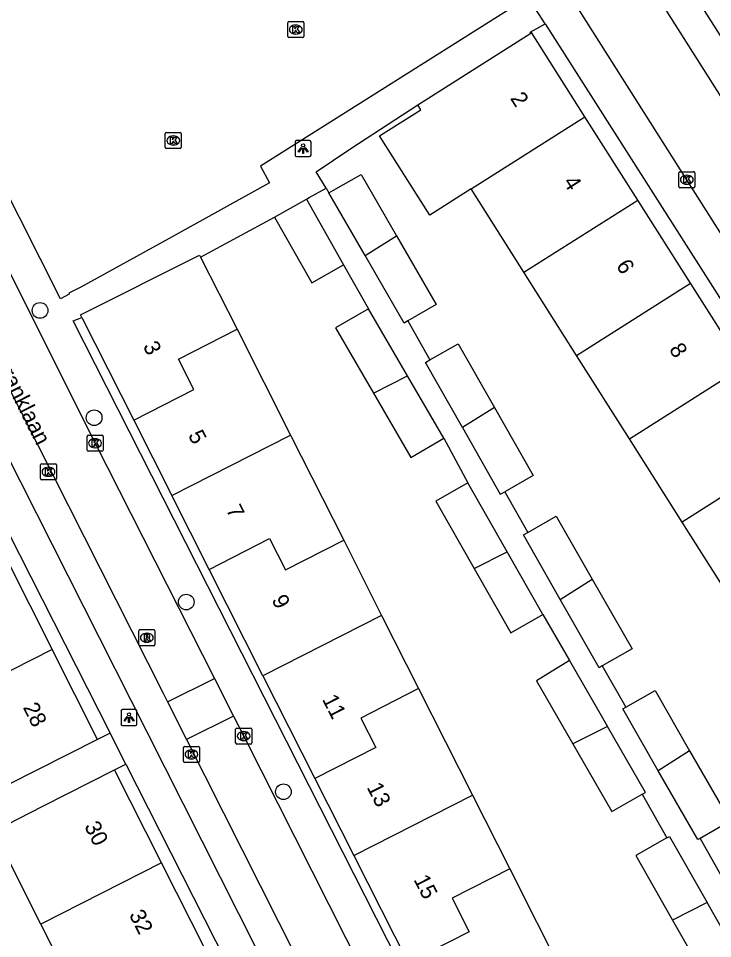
# Model space of a CAD drawing. Extents: x 162347 to 162868, y 381221 to 381813.
# Drawn here: x 162450 to 162493.3, y 381573.3 to 381630.7 of the extents above; entities that cross this region are included whole.
import ezdxf

# ---------------------------------------------------------------- set-up
doc = ezdxf.new("R2010")
doc.units = 0
for name, color, linetype in [('IMGEO_Boom', 7, 'Continuous'), ('IMGEO_Kolk', 7, 'Continuous'), ('IMGEO_Lichtpunt', 7, 'Continuous'), ('IMGEO_Openbare_ruimte_label', 7, 'Continuous'), ('IMGEO_Pand', 7, 'Continuous'), ('IMGEO_Pand_nummerreeks', 7, 'Continuous'), ('IMGEO_Rijbaan_lokaal_open', 7, 'Continuous'), ('IMGEO_Rioolput', 7, 'Continuous'), ('IMGEO_Voetpad_open', 7, 'Continuous')]:
    doc.layers.add(name, color=color, linetype=linetype)

msp = doc.modelspace()

# ---------------------------------------------------------------- linework, layer by layer
at = {"layer": 'IMGEO_Boom'}
for centre in [(162451.361, 381612.464), (162454.735, 381605.783), (162460.478, 381594.297), (162466.534, 381582.476)]:
    msp.add_circle(centre, 0.489, dxfattribs=at)
at = {"layer": 'IMGEO_Kolk'}
for p, q in [((162466.806, 381629.542), (162466.806, 381630.394)), ((162466.881, 381630.468), (162467.733, 381630.468)), ((162467.294, 381630.248), (162467.319, 381630.248)), ((162467.807, 381630.394), (162467.807, 381629.542)), ((162467.733, 381629.468), (162466.881, 381629.468)), ((162467.317, 381629.688), (162467.292, 381629.688)), ((162459.167, 381622.632), (162459.167, 381623.484)), ((162459.242, 381623.558), (162460.094, 381623.558)), ((162459.655, 381623.338), (162459.68, 381623.338)), ((162460.168, 381623.484), (162460.168, 381622.632)), ((162460.094, 381622.558), (162459.242, 381622.558)), ((162459.678, 381622.778), (162459.653, 381622.778)), ((162491.186, 381620.187), (162491.186, 381621.039)), ((162491.261, 381621.113), (162492.113, 381621.113)), ((162491.674, 381620.893), (162491.699, 381620.893)), ((162492.187, 381621.039), (162492.187, 381620.187)), ((162491.697, 381620.333), (162491.672, 381620.333)), ((162492.113, 381620.113), (162491.261, 381620.113)), ((162454.293, 381603.768), (162454.293, 381604.62)), ((162454.368, 381604.694), (162455.22, 381604.694)), ((162454.781, 381604.474), (162454.806, 381604.474)), ((162455.294, 381604.62), (162455.294, 381603.768)), ((162455.22, 381603.694), (162454.368, 381603.694)), ((162454.804, 381603.914), (162454.779, 381603.914)), ((162451.389, 381601.986), (162451.389, 381602.838)), ((162451.464, 381602.912), (162452.316, 381602.912)), ((162451.877, 381602.692), (162451.902, 381602.692)), ((162452.39, 381602.838), (162452.39, 381601.986)), ((162452.316, 381601.912), (162451.464, 381601.912)), ((162451.9, 381602.132), (162451.875, 381602.132)), ((162463.633, 381586.448), (162464.485, 381586.448)), ((162463.558, 381585.522), (162463.558, 381586.374)), ((162464.046, 381586.228), (162464.071, 381586.228)), ((162464.559, 381586.374), (162464.559, 381585.522)), ((162460.3, 381584.38), (162460.3, 381585.232)), ((162460.375, 381585.306), (162461.227, 381585.306)), ((162461.301, 381585.232), (162461.301, 381584.38)), ((162464.485, 381585.448), (162463.633, 381585.448)), ((162464.069, 381585.668), (162464.044, 381585.668)), ((162460.788, 381585.086), (162460.813, 381585.086)), ((162461.227, 381584.306), (162460.375, 381584.306)), ((162460.811, 381584.526), (162460.786, 381584.526))]:
    msp.add_line(p, q, dxfattribs=at)
for points in [[(162466.806, 381629.542), (162466.806, 381630.394)], [(162466.881, 381630.468), (162467.733, 381630.468)], [(162467.127, 381630.168), (162467.25, 381630.168), (162467.25, 381630.017), (162467.38, 381630.168), (162467.544, 381630.168), (162467.398, 381630.017), (162467.551, 381629.768), (162467.399, 381629.768), (162467.314, 381629.932), (162467.25, 381629.865), (162467.25, 381629.768), (162467.127, 381629.768), (162467.127, 381630.168)], [(162467.807, 381630.394), (162467.807, 381629.542)], [(162467.733, 381629.468), (162466.881, 381629.468)], [(162459.167, 381622.632), (162459.167, 381623.484)], [(162459.242, 381623.558), (162460.094, 381623.558)], [(162459.488, 381623.258), (162459.611, 381623.258), (162459.611, 381623.107), (162459.741, 381623.258), (162459.905, 381623.258), (162459.759, 381623.107), (162459.912, 381622.858), (162459.76, 381622.858), (162459.675, 381623.022), (162459.611, 381622.955), (162459.611, 381622.858), (162459.488, 381622.858), (162459.488, 381623.258)], [(162460.168, 381623.484), (162460.168, 381622.632)], [(162460.094, 381622.558), (162459.242, 381622.558)], [(162491.186, 381620.187), (162491.186, 381621.039)], [(162491.261, 381621.113), (162492.113, 381621.113)], [(162491.507, 381620.813), (162491.63, 381620.813), (162491.63, 381620.662), (162491.76, 381620.813), (162491.924, 381620.813), (162491.778, 381620.662), (162491.931, 381620.413), (162491.779, 381620.413), (162491.694, 381620.577), (162491.63, 381620.51), (162491.63, 381620.413), (162491.507, 381620.413), (162491.507, 381620.813)], [(162492.187, 381621.039), (162492.187, 381620.187)], [(162492.113, 381620.113), (162491.261, 381620.113)], [(162454.293, 381603.768), (162454.293, 381604.62)], [(162454.368, 381604.694), (162455.22, 381604.694)], [(162454.614, 381604.394), (162454.737, 381604.394), (162454.737, 381604.243), (162454.867, 381604.394), (162455.031, 381604.394), (162454.885, 381604.243), (162455.038, 381603.994), (162454.886, 381603.994), (162454.801, 381604.158), (162454.737, 381604.091), (162454.737, 381603.994), (162454.614, 381603.994), (162454.614, 381604.394)], [(162455.294, 381604.62), (162455.294, 381603.768)], [(162455.22, 381603.694), (162454.368, 381603.694)], [(162451.389, 381601.986), (162451.389, 381602.838)], [(162451.464, 381602.912), (162452.316, 381602.912)], [(162451.71, 381602.612), (162451.833, 381602.612), (162451.833, 381602.461), (162451.963, 381602.612), (162452.127, 381602.612), (162451.981, 381602.461), (162452.134, 381602.212), (162451.982, 381602.212), (162451.897, 381602.376), (162451.833, 381602.309), (162451.833, 381602.212), (162451.71, 381602.212), (162451.71, 381602.612)], [(162452.39, 381602.838), (162452.39, 381601.986)], [(162452.316, 381601.912), (162451.464, 381601.912)], [(162463.633, 381586.448), (162464.485, 381586.448)], [(162463.558, 381585.522), (162463.558, 381586.374)], [(162463.879, 381586.148), (162464.002, 381586.148), (162464.002, 381585.997), (162464.132, 381586.148), (162464.296, 381586.148), (162464.15, 381585.997), (162464.303, 381585.748), (162464.151, 381585.748), (162464.066, 381585.912), (162464.002, 381585.845), (162464.002, 381585.748), (162463.879, 381585.748), (162463.879, 381586.148)], [(162464.559, 381586.374), (162464.559, 381585.522)], [(162460.3, 381584.38), (162460.3, 381585.232)], [(162460.375, 381585.306), (162461.227, 381585.306)], [(162461.301, 381585.232), (162461.301, 381584.38)], [(162464.485, 381585.448), (162463.633, 381585.448)], [(162460.621, 381585.006), (162460.744, 381585.006), (162460.744, 381584.855), (162460.874, 381585.006), (162461.038, 381585.006), (162460.892, 381584.855), (162461.045, 381584.606), (162460.893, 381584.606), (162460.808, 381584.77), (162460.744, 381584.703), (162460.744, 381584.606), (162460.621, 381584.606), (162460.621, 381585.006)], [(162461.227, 381584.306), (162460.375, 381584.306)]]:
    msp.add_lwpolyline(points, dxfattribs=at)
for centre, start, end in [((162466.883, 381630.392), 91.55205, 178.44795), ((162466.883, 381630.392), 91.55205, 178.44795), ((162467.731, 381630.392), 1.55205, 88.44795), ((162467.731, 381630.392), 1.55205, 88.44795), ((162466.883, 381629.544), 181.55205, 268.44795), ((162466.883, 381629.544), 181.55205, 268.44795), ((162467.731, 381629.544), 271.55205, 358.44795), ((162467.731, 381629.544), 271.55205, 358.44795), ((162459.244, 381623.482), 91.55205, 178.44795), ((162459.244, 381623.482), 91.55205, 178.44795), ((162460.092, 381623.482), 1.55205, 88.44795), ((162460.092, 381623.482), 1.55205, 88.44795), ((162459.244, 381622.634), 181.55205, 268.44795), ((162459.244, 381622.634), 181.55205, 268.44795), ((162460.092, 381622.634), 271.55205, 358.44795), ((162460.092, 381622.634), 271.55205, 358.44795), ((162491.263, 381621.037), 91.55205, 178.44795), ((162491.263, 381621.037), 91.55205, 178.44795), ((162492.111, 381621.037), 1.55205, 88.44795), ((162492.111, 381621.037), 1.55205, 88.44795), ((162491.263, 381620.189), 181.55205, 268.44795), ((162491.263, 381620.189), 181.55205, 268.44795), ((162492.111, 381620.189), 271.55205, 358.44795), ((162492.111, 381620.189), 271.55205, 358.44795), ((162454.37, 381604.618), 91.55205, 178.44795), ((162454.37, 381604.618), 91.55205, 178.44795), ((162455.218, 381604.618), 1.55205, 88.44795), ((162455.218, 381604.618), 1.55205, 88.44795), ((162454.37, 381603.77), 181.55205, 268.44795), ((162454.37, 381603.77), 181.55205, 268.44795), ((162455.218, 381603.77), 271.55205, 358.44795), ((162455.218, 381603.77), 271.55205, 358.44795), ((162451.466, 381602.836), 91.55205, 178.44795), ((162451.466, 381602.836), 91.55205, 178.44795), ((162452.314, 381602.836), 1.55205, 88.44795), ((162452.314, 381602.836), 1.55205, 88.44795), ((162451.466, 381601.988), 181.55205, 268.44795), ((162451.466, 381601.988), 181.55205, 268.44795), ((162452.314, 381601.988), 271.55205, 358.44795), ((162452.314, 381601.988), 271.55205, 358.44795), ((162463.635, 381586.372), 91.55205, 178.44795), ((162463.635, 381586.372), 91.55205, 178.44795), ((162464.483, 381586.372), 1.55205, 88.44795), ((162464.483, 381586.372), 1.55205, 88.44795), ((162460.377, 381585.23), 91.55205, 178.44795), ((162460.377, 381585.23), 91.55205, 178.44795), ((162461.225, 381585.23), 1.55205, 88.44795), ((162461.225, 381585.23), 1.55205, 88.44795), ((162463.635, 381585.524), 181.55205, 268.44795), ((162463.635, 381585.524), 181.55205, 268.44795), ((162464.483, 381585.524), 271.55205, 358.44795), ((162464.483, 381585.524), 271.55205, 358.44795), ((162460.377, 381584.382), 181.55205, 268.44795), ((162460.377, 381584.382), 181.55205, 268.44795), ((162461.225, 381584.382), 271.55205, 358.44795), ((162461.225, 381584.382), 271.55205, 358.44795)]:
    msp.add_arc(centre, 0.0765, start, end, dxfattribs=at)
for centre, major_axis, ratio, start_param, end_param in [((162467.293, 381629.968), (-0.387, 0.002), 0.722429, 4.712389, 7.853982), ((162467.318, 381629.968), (-0.39, 0.002), 0.717154, 1.570796, 4.712389), ((162459.654, 381623.058), (-0.387, 0.002), 0.722429, 4.712389, 7.853982), ((162459.679, 381623.058), (-0.39, 0.002), 0.717154, 1.570796, 4.712389), ((162491.673, 381620.613), (-0.387, 0.002), 0.722429, 4.712389, 7.853982), ((162491.698, 381620.613), (-0.39, 0.002), 0.717154, 1.570796, 4.712389), ((162454.78, 381604.194), (-0.387, 0.002), 0.722429, 4.712389, 7.853982), ((162454.805, 381604.194), (-0.39, 0.002), 0.717154, 1.570796, 4.712389), ((162451.876, 381602.412), (-0.387, 0.002), 0.722429, 4.712389, 7.853982), ((162451.901, 381602.412), (-0.39, 0.002), 0.717154, 1.570796, 4.712389), ((162464.045, 381585.948), (-0.387, 0.002), 0.722429, 4.712389, 7.853982), ((162464.07, 381585.948), (-0.39, 0.002), 0.717154, 1.570796, 4.712389), ((162460.787, 381584.806), (-0.387, 0.002), 0.722429, 4.712389, 7.853982), ((162460.812, 381584.806), (-0.39, 0.002), 0.717154, 1.570796, 4.712389)]:
    msp.add_ellipse(centre, major_axis=major_axis, ratio=ratio, start_param=start_param, end_param=end_param, dxfattribs=at)
at = {"layer": 'IMGEO_Lichtpunt'}
for p, q in [((162467.265, 381622.955), (162467.265, 381622.148)), ((162467.265, 381622.955), (162467.265, 381622.148)), ((162468.167, 381623.05), (162467.359, 381623.05)), ((162468.167, 381623.05), (162467.359, 381623.05)), ((162468.261, 381622.148), (162468.261, 381622.955)), ((162468.261, 381622.148), (162468.261, 381622.955)), ((162467.359, 381622.054), (162468.167, 381622.054)), ((162467.359, 381622.054), (162468.167, 381622.054)), ((162457.312, 381587.598), (162456.504, 381587.598)), ((162457.312, 381587.598), (162456.504, 381587.598)), ((162456.41, 381587.503), (162456.41, 381586.696)), ((162456.41, 381587.503), (162456.41, 381586.696)), ((162457.406, 381586.696), (162457.406, 381587.503)), ((162457.406, 381586.696), (162457.406, 381587.503)), ((162456.504, 381586.602), (162457.312, 381586.602)), ((162456.504, 381586.602), (162457.312, 381586.602))]:
    msp.add_line(p, q, dxfattribs=at)
for points in [[(162467.639, 381622.619), (162467.678, 381622.591), (162467.49, 381622.329), (162467.452, 381622.356), (162467.639, 381622.619)], [(162467.741, 381622.571), (162467.788, 381622.571), (162467.788, 381622.249), (162467.741, 381622.249), (162467.741, 381622.571)], [(162467.851, 381622.591), (162467.889, 381622.618), (162468.076, 381622.356), (162468.037, 381622.328), (162467.851, 381622.591)], [(162456.784, 381587.167), (162456.823, 381587.139), (162456.635, 381586.877), (162456.597, 381586.904), (162456.784, 381587.167)], [(162456.886, 381587.119), (162456.933, 381587.119), (162456.933, 381586.797), (162456.886, 381586.797), (162456.886, 381587.119)], [(162456.996, 381587.139), (162457.034, 381587.166), (162457.221, 381586.904), (162457.182, 381586.876), (162456.996, 381587.139)]]:
    msp.add_lwpolyline(points, dxfattribs=at)
for centre in [(162467.764, 381622.753), (162456.909, 381587.301)]:
    msp.add_circle(centre, 0.0994, dxfattribs=at)
for centre, start, end in [((162467.359, 381622.955), 90, 180), ((162467.359, 381622.955), 90, 180), ((162468.167, 381622.955), 0, 90), ((162468.167, 381622.955), 0, 90), ((162467.359, 381622.148), 180, 270), ((162467.359, 381622.148), 180, 270), ((162468.167, 381622.148), 270, 0), ((162468.167, 381622.148), 270, 360), ((162456.504, 381587.503), 90, 180), ((162456.504, 381587.503), 90, 180), ((162457.312, 381587.503), 0, 90), ((162457.312, 381587.503), 0, 90), ((162456.504, 381586.696), 180, 270), ((162456.504, 381586.696), 180, 270), ((162457.312, 381586.696), 270, 0), ((162457.312, 381586.696), 270, 360)]:
    msp.add_arc(centre, 0.0946, start, end, dxfattribs=at)
at = {"layer": 'IMGEO_Pand'}
for points in [[(162474.912, 381625.272), (162481.958, 381629.752)], [(162485.338, 381624.533), (162482.007, 381629.783), (162481.958, 381629.752)], [(162478.233, 381620.036), (162475.66, 381618.407), (162472.535, 381623.344), (162475.104, 381624.97), (162474.912, 381625.272)], [(162478.233, 381620.036), (162485.338, 381624.533)], [(162488.628, 381619.345), (162485.338, 381624.533)], [(162469.374, 381619.791), (162469.667, 381619.96), (162471.374, 381620.947), (162473.587, 381617.121)], [(162471.633, 381615.885), (162469.374, 381619.791)], [(162481.524, 381614.848), (162478.233, 381620.036)], [(162465.983, 381618.274), (162467.97, 381619.402)], [(162467.97, 381619.402), (162470.291, 381615.313)], [(162481.524, 381614.848), (162488.628, 381619.345)], [(162491.92, 381614.157), (162488.628, 381619.345)], [(162465.983, 381618.274), (162468.304, 381614.185), (162470.291, 381615.313)], [(162471.633, 381615.885), (162473.587, 381617.121)], [(162473.587, 381617.121), (162476.065, 381612.836), (162474.293, 381611.811)], [(162453.968, 381612.034), (162453.886, 381612.196), (162461.304, 381615.919), (162461.371, 381615.787)], [(162461.371, 381615.787), (162463.643, 381611.293)], [(162474.293, 381611.811), (162474.065, 381611.679), (162471.633, 381615.885)], [(162484.816, 381609.66), (162481.524, 381614.848)], [(162484.816, 381609.66), (162491.92, 381614.157)], [(162495.211, 381608.969), (162491.92, 381614.157)], [(162471.848, 381612.568), (162469.793, 381611.376), (162472.148, 381607.316)], [(162474.269, 381608.394), (162471.848, 381612.568)], [(162453.968, 381612.034), (162457.202, 381605.637)], [(162457.202, 381605.637), (162460.957, 381607.545), (162459.995, 381609.44), (162463.643, 381611.293)], [(162463.643, 381611.293), (162466.981, 381604.692)], [(162475.673, 381609.382), (162477.433, 381610.385), (162479.687, 381606.428)], [(162477.693, 381605.165), (162475.385, 381609.218), (162475.673, 381609.382)], [(162488.107, 381604.472), (162484.816, 381609.66)], [(162488.107, 381604.472), (162495.211, 381608.969)], [(162472.148, 381607.316), (162474.269, 381608.394)], [(162476.527, 381604.501), (162474.269, 381608.394)], [(162472.148, 381607.316), (162474.472, 381603.309), (162476.527, 381604.501)], [(162479.687, 381606.428), (162477.693, 381605.165)], [(162479.687, 381606.428), (162482.106, 381602.183), (162480.333, 381601.172)], [(162457.202, 381605.637), (162459.581, 381600.933)], [(162477.693, 381605.165), (162480.057, 381601.015), (162480.333, 381601.172)], [(162459.581, 381600.933), (162466.981, 381604.692)], [(162466.981, 381604.692), (162470.293, 381598.143)], [(162491.398, 381599.284), (162488.107, 381604.472)], [(162498.502, 381603.78), (162491.398, 381599.284)], [(162478.042, 381601.722), (162476.04, 381600.582), (162478.428, 381596.391)], [(162480.484, 381597.435), (162478.042, 381601.722)], [(162461.906, 381596.335), (162459.581, 381600.933)], [(162481.776, 381598.631), (162483.545, 381599.644), (162485.787, 381595.732)], [(162494.689, 381594.096), (162491.398, 381599.284)], [(162483.788, 381594.466), (162481.504, 381598.475), (162481.776, 381598.631)], [(162461.906, 381596.335), (162465.678, 381598.251), (162466.668, 381596.301), (162470.293, 381598.143)], [(162470.293, 381598.143), (162472.661, 381593.461)], [(162478.428, 381596.391), (162480.484, 381597.435)], [(162482.714, 381593.52), (162480.484, 381597.435)], [(162449.333, 381596.861), (162452.128, 381591.331)], [(162465.26, 381589.702), (162461.906, 381596.335)], [(162478.428, 381596.391), (162480.712, 381592.38), (162482.714, 381593.52)], [(162483.788, 381594.466), (162485.787, 381595.732)], [(162485.787, 381595.732), (162488.277, 381591.387), (162486.413, 381590.318)], [(162486.413, 381590.318), (162486.215, 381590.205), (162483.788, 381594.466)], [(162472.661, 381593.461), (162465.26, 381589.702)], [(162472.661, 381593.461), (162474.966, 381588.902)], [(162452.128, 381591.331), (162444.624, 381587.534)], [(162454.951, 381585.737), (162452.128, 381591.331)], [(162484.371, 381590.657), (162482.325, 381589.39), (162484.59, 381585.457)], [(162484.371, 381590.657), (162486.738, 381586.548)], [(162465.26, 381589.702), (162468.494, 381583.305)], [(162474.966, 381588.902), (162471.357, 381587.069), (162472.29, 381585.233), (162468.494, 381583.305)], [(162474.966, 381588.902), (162478.319, 381582.273)], [(162487.877, 381587.739), (162489.705, 381588.788), (162491.864, 381585.027)], [(162489.908, 381583.789), (162487.698, 381587.636), (162487.877, 381587.739)], [(162486.738, 381586.548), (162484.59, 381585.457)], [(162488.904, 381582.325), (162489.104, 381582.44), (162486.738, 381586.548)], [(162454.951, 381585.737), (162447.443, 381581.948)], [(162484.59, 381585.457), (162487.019, 381581.24), (162488.904, 381582.325)], [(162491.864, 381585.027), (162489.908, 381583.789)], [(162491.864, 381585.027), (162494.38, 381580.647), (162492.512, 381579.574)], [(162448.475, 381580.031), (162451.541, 381581.582), (162456.002, 381583.84)], [(162458.935, 381578.045), (162456.002, 381583.84)], [(162492.512, 381579.574), (162492.374, 381579.495), (162489.908, 381583.789)], [(162468.494, 381583.305), (162470.917, 381578.514)], [(162470.917, 381578.514), (162478.319, 381582.273)], [(162478.319, 381582.273), (162480.644, 381577.675)], [(162451.409, 381574.236), (162448.475, 381580.031)], [(162490.45, 381579.607), (162488.505, 381578.498), (162490.799, 381574.472)], [(162490.45, 381579.607), (162490.611, 381579.698), (162492.949, 381575.568)], [(162470.917, 381578.514), (162474.308, 381571.807)], [(162458.935, 381578.045), (162451.409, 381574.236)], [(162461.717, 381572.548), (162458.935, 381578.045)], [(162480.644, 381577.675), (162477.054, 381575.852), (162478.124, 381573.745), (162474.308, 381571.807)], [(162480.644, 381577.675), (162484.006, 381571.026)], [(162492.949, 381575.568), (162490.799, 381574.472)], [(162495.112, 381571.395), (162495.286, 381571.494), (162492.949, 381575.568)], [(162490.799, 381574.472), (162493.18, 381570.294), (162495.112, 381571.395)], [(162454.192, 381568.74), (162451.409, 381574.236)]]:
    msp.add_lwpolyline(points, dxfattribs=at)
at = {"layer": 'IMGEO_Rijbaan_lokaal_open'}
for points in [[(162425.373, 381654.562), (162435.395, 381635.369), (162459.045, 381588.618), (162459.315, 381588.084)], [(162477.262, 381651.857), (162493.957, 381625.539)], [(162431.784, 381649.823), (162438.386, 381636.782), (162446.504, 381620.717), (162454.794, 381604.194), (162462.238, 381589.534)], [(162502.811, 381603.082), (162500.464, 381606.783), (162491.687, 381620.613), (162482.235, 381635.536), (162480.538, 381638.212)], [(162459.315, 381588.084), (162462.238, 381589.534)], [(162462.238, 381589.534), (162463.431, 381587.185)], [(162459.315, 381588.084), (162460.5, 381585.739)], [(162463.431, 381587.185), (162460.5, 381585.739)], [(162463.431, 381587.185), (162464.059, 381585.948), (162471.49, 381571.265), (162480.304, 381553.954), (162489.2, 381536.187)], [(162460.5, 381585.739), (162491.571, 381524.186)]]:
    msp.add_lwpolyline(points, dxfattribs=at)
at = {"layer": 'IMGEO_Rioolput'}
for p, q in [((162457.521, 381591.65), (162457.521, 381592.502)), ((162457.596, 381592.576), (162458.448, 381592.576)), ((162458.009, 381592.356), (162458.034, 381592.356)), ((162458.522, 381592.502), (162458.522, 381591.65)), ((162458.448, 381591.576), (162457.596, 381591.576)), ((162458.032, 381591.796), (162458.007, 381591.796))]:
    msp.add_line(p, q, dxfattribs=at)
for points in [[(162457.521, 381591.65), (162457.521, 381592.502)], [(162457.596, 381592.576), (162458.448, 381592.576)], [(162458.11, 381592.274), (162457.858, 381592.276), (162457.858, 381591.876)], [(162458.036, 381592.195), (162457.982, 381592.195), (162457.982, 381592.114)], [(162457.982, 381592.114), (162458.034, 381592.114)], [(162458.522, 381592.502), (162458.522, 381591.65)], [(162458.448, 381591.576), (162457.596, 381591.576)], [(162457.858, 381591.876), (162457.982, 381591.876), (162457.982, 381592.038), (162457.993, 381592.038)], [(162458.04, 381592.009), (162458.111, 381591.876), (162458.251, 381591.876), (162458.186, 381592.002)]]:
    msp.add_lwpolyline(points, dxfattribs=at)
for centre, radius, start, end in [((162457.598, 381592.5), 0.0765, 91.55205, 178.44795), ((162457.598, 381592.5), 0.0765, 91.55205, 178.44795), ((162458.018, 381592.303), 0.19, 274.7715, 282.96867), ((162458.042, 381592.099), 0.0964, 77.00612, 93.18647), ((162458.056, 381592.156), 0.0378, 276.66336, 79.67722), ((162458.109, 381592.164), 0.109, 350.36119, 89.41601), ((162458.107, 381592.164), 0.112, 277.58423, 350.98172), ((162458.446, 381592.5), 0.0765, 1.55205, 88.44795), ((162458.446, 381592.5), 0.0765, 1.55205, 88.44795), ((162457.598, 381591.652), 0.0765, 181.55205, 268.44795), ((162457.598, 381591.652), 0.0765, 181.55205, 268.44795), ((162457.992, 381591.985), 0.0533, 26.02933, 88.69889), ((162458.091, 381591.949), 0.108, 29.51342, 73.79051), ((162458.446, 381591.652), 0.0765, 271.55205, 358.44795), ((162458.446, 381591.652), 0.0765, 271.55205, 358.44795)]:
    msp.add_arc(centre, radius, start, end, dxfattribs=at)
for centre, major_axis, ratio, start_param, end_param in [((162458.008, 381592.076), (-0.387, 0.002), 0.722429, 4.712389, 7.853982), ((162458.033, 381592.076), (-0.39, 0.002), 0.717154, 1.570796, 4.712389)]:
    msp.add_ellipse(centre, major_axis=major_axis, ratio=ratio, start_param=start_param, end_param=end_param, dxfattribs=at)
at = {"layer": 'IMGEO_Voetpad_open'}
for points in [[(162481.795, 381631.988), (162465.1, 381621.456), (162465.658, 381620.415), (162459.405, 381616.959), (162453.909, 381613.922), (162453.166, 381613.535), (162453.177, 381613.49), (162452.631, 381613.197), (162432.233, 381653.635), (162431.972, 381654.923), (162436.115, 381656.689), (162435.222, 381659.331), (162439.544, 381661.021), (162442.545, 381663.577), (162445.27, 381668.731), (162448.302, 381667.139), (162451.197, 381672.343), (162452.016, 381672.565)], [(162415.849, 381663.025), (162416.703, 381663.475), (162450.084, 381597.259), (162455.733, 381586.132)], [(162488.481, 381525.898), (162484.409, 381533.947), (162458.021, 381586.227), (162433.476, 381634.757), (162424.757, 381651.992)], [(162480.123, 381651.083), (162495.26, 381627.225)], [(162482.857, 381630.326), (162481.795, 381631.988)], [(162481.958, 381629.752), (162481.918, 381629.814), (162482.857, 381630.326)], [(162482.857, 381630.326), (162500, 381603.428), (162522.094, 381568.761), (162522.773, 381567.696)], [(162469.201, 381620.077), (162468.584, 381621.093), (162470.747, 381622.562), (162474.912, 381625.272)], [(162467.97, 381619.402), (162468.147, 381619.499), (162469.201, 381620.077)], [(162469.201, 381620.077), (162469.374, 381619.791)], [(162461.371, 381615.787), (162465.983, 381618.274)], [(162470.291, 381615.313), (162471.848, 381612.568)], [(162493.857, 381533.592), (162493.913, 381533.481), (162493.347, 381533.215), (162453.435, 381611.809), (162453.968, 381612.034)], [(162474.293, 381611.811), (162475.673, 381609.382)], [(162476.527, 381604.501), (162478.042, 381601.722)], [(162480.333, 381601.172), (162481.776, 381598.631)], [(162482.714, 381593.52), (162484.371, 381590.657)], [(162486.413, 381590.318), (162487.877, 381587.739)], [(162455.733, 381586.132), (162454.951, 381585.737)], [(162456.714, 381584.2), (162455.733, 381586.132)], [(162456.002, 381583.84), (162456.714, 381584.2)], [(162456.714, 381584.2), (162490.31, 381518.027), (162489.593, 381517.672)], [(162488.904, 381582.325), (162490.45, 381579.607)], [(162492.512, 381579.574), (162493.898, 381577.132)]]:
    msp.add_lwpolyline(points, dxfattribs=at)

# ---------------------------------------------------------------- texts
at = {"layer": 'IMGEO_Openbare_ruimte_label'}
msp.add_text('Heggeranklaan', height=1, rotation=296.87254, dxfattribs=at).set_placement((162447.083, 381612.081))
at = {"layer": 'IMGEO_Pand_nummerreeks'}
for s, rotation, p in [('2', 302.3318, (162480.647, 381625.687)), ('4', 302.3318, (162483.947, 381620.473)), ('6', 302.3318, (162487.246, 381615.26)), ('3', 296.92308, (162457.755, 381610.245)), ('8', 302.3318, (162490.548, 381610.044)), ('5', 296.92308, (162460.57, 381604.702)), ('7', 296.92308, (162462.93, 381600.054)), ('9', 296.92308, (162465.779, 381594.444)), ('11', 296.92308, (162468.929, 381588.243)), ('28', 296.84286, (162450.274, 381587.738)), ('13', 296.92308, (162471.716, 381582.755)), ('30', 296.84199, (162454.1, 381580.335)), ('15', 296.92308, (162474.633, 381577.011)), ('32', 296.84199, (162456.889, 381574.823))]:
    msp.add_text(s, height=1, rotation=rotation, dxfattribs=at).set_placement(p)

doc.saveas('drawing.dxf')
